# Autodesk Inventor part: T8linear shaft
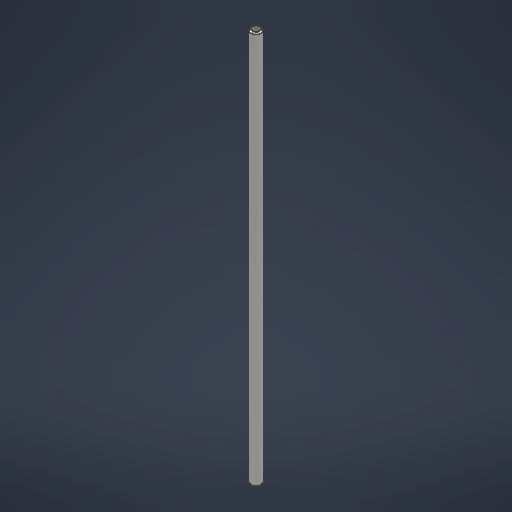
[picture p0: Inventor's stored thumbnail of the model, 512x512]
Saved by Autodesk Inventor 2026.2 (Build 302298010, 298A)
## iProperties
Created: 2026-04
Part Number: T8linear shaft
Material: 스테인리스스틸
Document SubType Name: Modeling
Designer: work
Density: 8 g/cm^3
Appearance: 반연마
Author: work
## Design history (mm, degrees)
sketch "스케치1"
  geometry: C1 r 4 at (0, 0); 1 further point
  constraints: 1 centre point, 1 coincident
  dimensions: "d0" = 8 diameter of C1
extrude "돌출1" new body sketch "스케치1" distance "d1" = 300; taper "d2" = 0 deg
chamfer "모따기1" distance "d3" = 1; stored, may be unused: second distance "d4" = 2, angle "d5" = 45 deg
node "솔리드1"
